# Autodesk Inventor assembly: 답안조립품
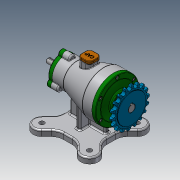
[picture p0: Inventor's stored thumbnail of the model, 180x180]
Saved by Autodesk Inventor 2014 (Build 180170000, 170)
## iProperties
Created: 2018-03
Part Number: 답안조립품
Document SubType Name: Assembly
Designer: NET
Author: NET
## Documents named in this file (15)
- C:\Users\NET\Desktop\480307V1013\답안조립품.iam
- C:\Users\NET\Desktop\480307V1013\뒤커버.ipt
- C:\Users\NET\Desktop\480307V1013\마개.ipt
- C:\Users\NET\Desktop\480307V1013\베어링-6200.ipt
- C:\Users\NET\Desktop\480307V1013\베어링-6203.ipt
- C:\Users\NET\Desktop\480307V1013\본체.ipt
- C:\Users\NET\Desktop\480307V1013\볼트 M4 x 12.ipt
- 볼트 M4 x 12.ipt
- C:\Users\NET\Desktop\480307V1013\스프로킷.ipt
- C:\Users\NET\Desktop\480307V1013\앞커버.ipt
- C:\Users\NET\Desktop\480307V1013\오일 실 10 20 7.ipt
- C:\Users\NET\Desktop\480307V1013\오일 실 17 30 8.ipt
- C:\Users\NET\Desktop\480307V1013\축.ipt
- C:\Users\NET\Desktop\480307V1013\키 5 x 5.ipt
- 키 5 x 5.ipt
